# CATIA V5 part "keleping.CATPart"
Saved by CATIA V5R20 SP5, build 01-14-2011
Part number: 可乐瓶
Material "无"
Material "Copper": density 8900 kg/m3, Young's modulus 1.1e+11 Pa, Poisson ratio 0.33, thermal expansion 1.65e-05 1/K
Material "Copper": density 8900 kg/m3, Young's modulus 1.1e+11 Pa, Poisson ratio 0.33, thermal expansion 1.65e-05 1/K
Material "Copper": density 8900 kg/m3, Young's modulus 1.1e+11 Pa, Poisson ratio 0.33, thermal expansion 1.65e-05 1/K
Material "Copper": density 8900 kg/m3, Young's modulus 1.1e+11 Pa, Poisson ratio 0.33, thermal expansion 1.65e-05 1/K
Material "Copper": density 8900 kg/m3, Young's modulus 1.1e+11 Pa, Poisson ratio 0.33, thermal expansion 1.65e-05 1/K
Bounding box of the stored display mesh (mm): x -25 to 25, y -25 to 25, z 0 to 140
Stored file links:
  E:\姜浩然03.08\keleping.CATPart
  C:\Program Files\Dassault Systemes\B20\intel_a\startup\materials\Catalog.CATMaterial
  C:\Program Files\Dassault Systemes\B20\intel_a\startup\materials\DS_star.jpg
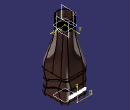
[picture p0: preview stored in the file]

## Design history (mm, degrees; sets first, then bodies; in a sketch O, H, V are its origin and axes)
Set1
  Sketch1 on xy-plane, origin (0, 0, 0), H (1, 0, 0), V (0, 1, 0)
    line L1 (25, 25) -> (25, -25)
    line L2 (25, -25) -> (-25, -25)
    line L3 (-25, -25) -> (-25, 25)
    line L4 (-25, 25) -> (25, 25)
    length L1 = 50
    length L4 = 50
    vertical: L1 V, L3 V
    horizontal: L2 H, L4 H
    equidistance: L1 L3 O, L2 L4 O
  Sketch2 on face of Pad1 from Sketch1.L1, origin (25, 0, 0), H (0, 1, 0), V (0, 0, 1)
    spline S1 through (-58.735, 18.2067) (-40.2556, 26.4971) (-23.1622, 18.2067) (7.0978, 28.7999) (35.0479, 23.7336) (49.1385, 19.8187)
  Extrude1: Element1 Sketch2, Lim1 20, Lim2 68
  MultiSel1: CommonCtxFeats ({extract ExtractElem face of Pad1 from Sketch1.L1}; {extract ExtractElem face of Fillet1}; {extract ExtractElem face of Pad1 from Sketch1.L4}; {extract ExtractElem face of Fillet1}; {extract ExtractElem face of Pad1 from Sketch1.L3}; {extract ExtractElem face of Fillet1}; {extract ExtractElem face of Pad1 from Sketch1.L2}; {extract ExtractElem face of Fillet1})
  Sketch3 on face of Pad1 from Sketch1.L3, origin (-25, 0, 0), H (0, -1, 0), V (0, 0, 1)
    spline S1 through (-35.8059, 37.1066) (-18.9877, 46.135) (9.474, 34.5271) (39.7838, 39.1334) (43.665, 48.346)
  Extrude2: Element1 Sketch3, Lim1 20, Lim2 68
  MultiSel2: CommonCtxFeats ({extract ExtractElem face of Pad1 from Sketch1.L3}; {extract ExtractElem face of Fillet1}; {extract ExtractElem face of Pad1 from Sketch1.L2}; {extract ExtractElem face of Fillet1}; {extract ExtractElem face of Pad1 from Sketch1.L1}; {extract ExtractElem face of Fillet1}; {extract ExtractElem face of Pad1 from Sketch1.L4}; {extract ExtractElem face of Fillet1})
  Join1: Elements ({intersect ToIntersect1 {extract ExtractElem face of Pad1 from Sketch1.L3}, ToIntersect2 Extrude1}; {intersect ToIntersect1 {extract ExtractElem face of Fillet1}, ToIntersect2 Extrude1}; {intersect ToIntersect1 {extract ExtractElem face of Pad1 from Sketch1.L4}, ToIntersect2 Extrude1}; {intersect ToIntersect1 {extract ExtractElem face of Fillet1}, ToIntersect2 Extrude1}; {intersect ToIntersect1 {extract ExtractElem face of Pad1 from Sketch1.L1}, ToIntersect2 Extrude1}; {intersect ToIntersect1 {extract ExtractElem face of Pad1 from Sketch1.L2}, ToIntersect2 Extrude1}; {intersect ToIntersect1 {extract ExtractElem face of Fillet1}, ToIntersect2 Extrude1}; {intersect ToIntersect1 {extract ExtractElem face of Fillet1}, ToIntersect2 Extrude1})
  Join2: Elements ({intersect ToIntersect1 {extract ExtractElem face of Pad1 from Sketch1.L3}, ToIntersect2 Extrude2}; {intersect ToIntersect1 {extract ExtractElem face of Fillet1}, ToIntersect2 Extrude2}; {intersect ToIntersect1 {extract ExtractElem face of Fillet1}, ToIntersect2 Extrude2}; {intersect ToIntersect1 {extract ExtractElem face of Pad1 from Sketch1.L2}, ToIntersect2 Extrude2}; {intersect ToIntersect1 {extract ExtractElem face of Fillet1}, ToIntersect2 Extrude2}; {intersect ToIntersect1 {extract ExtractElem face of Pad1 from Sketch1.L1}, ToIntersect2 Extrude2}; {intersect ToIntersect1 {extract ExtractElem face of Fillet1}, ToIntersect2 Extrude2}; {intersect ToIntersect1 {extract ExtractElem face of Pad1 from Sketch1.L4}, ToIntersect2 Extrude2})
  Plane1: type Normal, Curve Join1, RefPoint vertex [face of MultiSel1 | face of MultiSel1]
  Circle1: type CtrRad, Start 0, End 180, Center vertex [face of MultiSel1 | face of MultiSel1], Support Plane1, Radius 1, FirstDirection (1, 0, 0)
Body1 (main body), material "Copper"
  Plane2: type Offset, RefPlane xy-plane, Offset 20
  Set2
    Plane3: type Offset, RefPlane xy-plane, Offset 40 {= Plane2.Offset+`Plane3.相对Offset`}
    Plane4: type Offset, RefPlane xy-plane, Offset 60 {= Plane3.Offset+`Plane4.相对Offset`}
    Plane5: type Offset, RefPlane xy-plane, Offset 80 {= Plane4.Offset+`Plane5.相对Offset`}
    Plane6: type Offset, RefPlane xy-plane, Offset 100 {= Plane5.Offset+`Plane6.相对Offset`}
    Plane7: type Offset, RefPlane xy-plane, Offset 120 {= Plane6.Offset+`Plane7.相对Offset`}
    Plane8: type Offset, RefPlane xy-plane, Offset 140 {= Plane7.Offset+`Plane8.相对Offset`}
    Plane9: type Offset, RefPlane xy-plane, Offset 160 {= Plane8.Offset+`Plane9.相对Offset`}
  Pad1: profile Sketch1, direction (0, 0, 1), length 50
  Fillet1: on edge [face of Pad1 from Sketch1.L1 | face of Pad1 from Sketch1.L2]; edge [face of Pad1 from Sketch1.L4 | face of Pad1 from Sketch1.L1]; edge [face of Pad1 from Sketch1.L2 | face of Pad1 from Sketch1.L3]; edge [face of Pad1 from Sketch1.L3 | face of Pad1 from Sketch1.L4]
  Fillet2: radius 8, on edge [start face of Pad1 | face of Pad1 from Sketch1.L3]
  Sketch4 on Plane7, origin (0, 0, 120), H (1, 0, 0), V (0, 1, 0)
    circle A1 centre (0, 0) radius 15
  Pad2: profile Sketch4, direction (0, 0, 1), length 20
  Sketch5 on end face of Pad1, origin (0, 0, 50), H (1, 0, 0), V (0, 1, 0)
    point P1 (25, 0)
    distance P1 O = 25
    coincidence: P1 H
  Sketch6 on start face of Pad2, origin (0, 0, 120), H (1, 0, 0), V (0, -1, 0)
    point P1 (15, 0)
    distance P1 V = 15
    coincidence: P1 H
  Loft1: solid, Sections ({boundary Boundary {extract ExtractElem start face of Pad2}}; {boundary Boundary {extract ExtractElem end face of Pad1}}), StartFace start face of Pad2, EndFace end face of Pad1
  Shell1: ExtOffset 0, Face end face of Pad2, IntOffset 1
  Slot1: profile Circle1, centre curve Join1
  Join3: Elements Join2
  Plane10: type Normal, Curve Join3, RefPoint vertex [face of MultiSel2 | face of MultiSel2]
  Circle2: type CtrRad, Start 0, End 180, Center vertex [face of MultiSel2 | face of MultiSel2], Support Plane10, Radius 1, FirstDirection (0, -1, 0)
  Slot2: profile Circle2, centre curve Join3
  Plane11: type Offset, RefPlane xy-plane, Offset 122
  Sketch7 on Plane11, origin (0, 0, 122), H (1, 0, 0), V (0, 1, 0)
    point P1 (15, 0)
    distance P1 V = 15
    coincidence: P1 H
  Helix1: Direction Z axis, RefPoint Sketch7, Pitch 2, Height 15, TaperAngle 0
  Body2
    Sketch8 on Plane11, origin (0, 0, 122), H (1, 0, 0), V (0, 1, 0)
      circle A1 centre (0, 0) radius 14
    Pad3: profile Sketch8, direction (0, 0, 1), length 30
  Remove1: tool Body2
  Body3, material "Copper"
    Sketch9 on face of Pad1 from Sketch1.L4, origin (0, 25, 0), H (-1, 0, 0), V (0, 0, 1)
      polyline C1
      polyline C2
      polyline C3
      polyline C4
      polyline C5
      polyline C6
      polyline C7
      polyline C8
      polyline C9
      polyline C10
      polyline C11
      polyline C12
      polyline C13
    Point1: type OnCurve, Support Helix1, RefPoint vertex of Helix1, Length -5
    Point2: type OnCurve, Support Helix1, RefPoint Sketch7, Length 5
    Line1: type PtDir, RefPoint Sketch7, Direction (1, 0, 0), Start 0, End 10
    Line2: type PtDir, RefPoint vertex of Helix1, Direction (1, 0, 0), Start 0, End 10
    Connect1: Curve1 Line1, Point1 vertex of Line1, Tension1 1, Curve2 Helix1, Point2 Point2, Tension2 1
    Connect2: Curve1 Line2, Point1 vertex of Line2, Tension1 1, Curve2 Connect1, Point2 Point1, Tension2 1
    Plane12: type OffsetPt, RefPlane yz-plane, RefPoint vertex of Connect2
    Plane13: type OffsetPt, RefPlane yz-plane, RefPoint vertex of Connect1
    Circle3: type CtrRad, Start 0, End 180, Radius 0.5, Center vertex of Connect1, Support Plane13, FirstDirection (0, 1, 0)
    Circle4: type CtrRad, Start 0, End 180, Radius 0.5, Center vertex of Connect2, Support Plane12, FirstDirection (0, 1, 0)
    Rib1: profile Circle3, centre curve Connect2
  Remove2: tool Body3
